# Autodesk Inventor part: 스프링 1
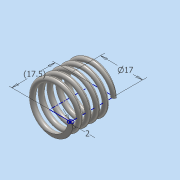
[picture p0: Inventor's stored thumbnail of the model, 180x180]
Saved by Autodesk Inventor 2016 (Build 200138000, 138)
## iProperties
Created: 2019-11
Part Number: 스프링 1
Material: 스테인레스 스틸
Document SubType Name: Modeling
Designer: user
Density: 8 g/cm^3
Appearance: 반연마
Mass: 6.54924 g
Surface Area: 16.7049 cm^2
Volume: 0.818655 cm^3
Author: user
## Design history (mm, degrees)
sketch "스케치1"
  geometry: L1 (0, 0)-(8.5, 0); L2 (8.5, 0)-(8.5, 17.5); L3 (8.5, 17.5)-(0, 17.5); L4 (0, 17.5)-(0, 0); C1 r 1 at (8.5, 0)
  constraints: 8 end point, 2 parallel, 1 centre point, 1 coincident, 1 horizontal, 1 perpendicular
  dimensions: "d1" = 17 diameter of L2 L4; "d2" = 2 diameter of C1; "d3" = 17.5 distance of L3.end L1.start (derived)
feature "코일1" sketch "스케치1" pitch "d4" = 10; turns "d6" = 5; dims "d5" = 17.5 (= d3), "d7" = 0, angle "d8" = 90 deg, angle "d9" = 90 deg, "d10" = 0, "d11" = 0
sketch "스케치2"
  geometry: L1 (-15, 17.5)-(15, 17.5); L2 (15, 17.5)-(15, 0); L3 (15, 0)-(-15, 0); L4 (-15, 0)-(-15, 17.5); 2 further points
  constraints: 8 end point, 2 parallel, 1 coincident, 1 horizontal, 1 midpoint, 1 perpendicular
  dimensions: "d12" = 17.5 distance of L3.end L1.start (= d3); "d13" = 30 distance of L1.start L1.end
extrude "돌출1" sketch "스케치2" stored distance "d14" = 117.5; taper "d15" = 0 deg
node "솔리드1"
